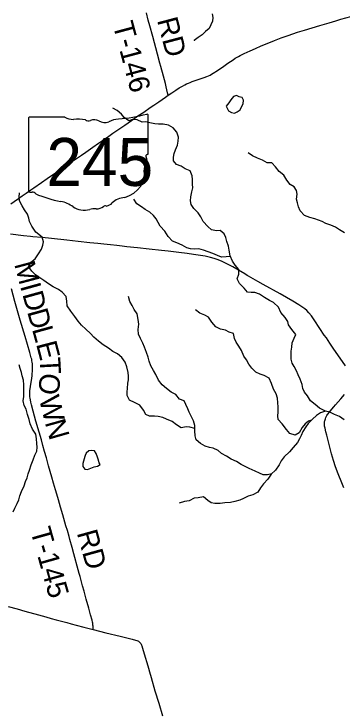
# Model space of a CAD drawing. Extents: x 0 to 1101, y 0 to 440.
# Drawn here: x 848.082 to 848.986, y 371.906 to 373.824 of the extents above; entities that cross this region are included whole.
import ezdxf

# ---------------------------------------------------------------- set-up
doc = ezdxf.new("R2010")
doc.units = 0
for name, color, linetype in [('GM_X_County_Road', 7, 'Continuous'), ('GM_X_Minor_Lake', 7, 'Continuous'), ('GM_X_Minor_River', 7, 'Continuous'), ('GM_X_State_Location', 7, 'Continuous'), ('GM_X_State_Route', 7, 'Continuous'), ('GM_X_State_Shield', 7, 'Continuous'), ('GM_X_Township_Road', 7, 'Continuous'), ('GM_X_Township_Road_Text', 7, 'Continuous')]:
    doc.layers.add(name, color=color, linetype=linetype)

msp = doc.modelspace()

# ---------------------------------------------------------------- linework, layer by layer
at = {"layer": 'GM_X_County_Road'}
for points in [[(848.9949, 372.8555), (848.9742, 372.8857), (848.9632, 372.9022), (848.9523, 372.9182), (848.9425, 372.9325), (848.9369, 372.9407), (848.9247, 372.9586), (848.9086, 372.9829), (848.9014, 372.9931), (848.8943, 373.0019), (848.8886, 373.0077), (848.8829, 373.0125), (848.8754, 373.0181), (848.8666, 373.024), (848.85, 373.034), (848.8148, 373.0538), (848.7687, 373.0795), (848.7536, 373.0881), (848.7284, 373.1027), (848.7246, 373.1049), (848.7176, 373.1089), (848.7005, 373.119), (848.6849, 373.128), (848.6701, 373.136), (848.6539, 373.1439), (848.6417, 373.1486), (848.6333, 373.1516), (848.6237, 373.1543), (848.6163, 373.1559), (848.6085, 373.1573), (848.5955, 373.1591), (848.5765, 373.1621), (848.5587, 373.1647), (848.5359, 373.1679), (848.5063, 373.1717), (848.4884, 373.1737), (848.4544, 373.1771), (848.4223, 373.1806), (848.3932, 373.1835), (848.3796, 373.185), (848.3654, 373.1868), (848.3475, 373.1888), (848.3296, 373.1906), (848.3129, 373.1925), (848.2913, 373.1947), (848.2591, 373.1982), (848.2276, 373.2016), (848.185, 373.206), (848.1769, 373.2068), (848.1584, 373.2086), (848.1336, 373.2112), (848.1275, 373.2118), (848.1077, 373.214), (848.0719, 373.2181)], [(848.9907, 372.5206), (848.985, 372.5343), (848.975, 372.5583), (848.9676, 372.578), (848.9619, 372.5951), (848.9565, 372.6141), (848.9493, 372.6431), (848.9438, 372.6648), (848.9412, 372.6744), (848.9389, 372.684), (848.9378, 372.69), (848.9373, 372.6948), (848.9372, 372.6975), (848.9374, 372.6998), (848.9378, 372.7024), (848.9382, 372.7048), (848.9388, 372.7075), (848.9397, 372.7103), (848.9408, 372.7133), (848.9421, 372.7158), (848.9436, 372.7188), (848.9453, 372.7216), (848.9465, 372.7233), (848.9526, 372.7311), (848.9633, 372.7432), (848.9678, 372.7483), (848.9825, 372.7652), (848.9926, 372.777)]]:
    msp.add_lwpolyline(points, dxfattribs=at)
at = {"layer": 'GM_X_Minor_Lake'}
for points in [[(848.7064, 373.5954), (848.7026, 373.5963), (848.6947, 373.5995), (848.6867, 373.5966), (848.679, 373.588), (848.6736, 373.5794), (848.6662, 373.5704)], [(848.6662, 373.5704), (848.6728, 373.5578), (848.6811, 373.5528), (848.6894, 373.5515), (848.697, 373.5544), (848.7046, 373.5604), (848.7089, 373.5686), (848.7129, 373.5772), (848.7145, 373.5867), (848.7109, 373.5943), (848.7064, 373.5954)], [(848.3192, 372.5848), (848.317, 372.589), (848.3138, 372.5989), (848.3116, 372.605), (848.3084, 372.6145), (848.304, 372.6221), (848.2957, 372.623), (848.2877, 372.6216), (848.2804, 372.6153), (848.2778, 372.6088)], [(848.2778, 372.6088), (848.2768, 372.6063), (848.272, 372.5875), (848.2718, 372.5788), (848.2774, 372.5715), (848.2849, 372.5707), (848.2937, 372.5747), (848.3028, 372.5779), (848.3116, 372.58), (848.3192, 372.5848)]]:
    msp.add_lwpolyline(points, dxfattribs=at)
at = {"layer": 'GM_X_Minor_River'}
for points in [[(848.6275, 373.8243), (848.6302, 373.8141), (848.6287, 373.8046), (848.6242, 373.794), (848.6192, 373.7845), (848.6098, 373.7761), (848.6003, 373.767), (848.5889, 373.7598), (848.5783, 373.7507), (848.5783, 373.7503)], [(848.9397, 372.7313), (848.9232, 372.7391), (848.9117, 372.7495), (848.899, 372.7599), (848.8909, 372.7736), (848.8827, 372.7836), (848.878, 372.7931), (848.8755, 372.8048), (848.8705, 372.8193), (848.8646, 372.8314), (848.8606, 372.8417), (848.854, 372.8539), (848.8481, 372.8634), (848.8453, 372.8744), (848.8451, 372.8869), (848.846, 372.8963), (848.847, 372.9068), (848.8487, 372.9189), (848.8538, 372.932), (848.8585, 372.9425), (848.8478, 372.9555), (848.8378, 372.9685), (848.8368, 372.9779), (848.8294, 372.989), (848.8172, 373.0024), (848.8106, 373.0176), (848.7972, 373.0299), (848.7859, 373.0354), (848.7725, 373.0443), (848.7586, 373.0532), (848.7451, 373.0579), (848.7353, 373.0581), (848.7251, 373.059), (848.7158, 373.0697), (848.7035, 373.0827), (848.6969, 373.0957), (848.7017, 373.1084), (848.7015, 373.1213), (848.6911, 373.1327), (848.6841, 373.1442), (848.6775, 373.1583), (848.6748, 373.1745), (848.6727, 373.1855), (848.6684, 373.1976), (848.6659, 373.2094), (848.6612, 373.2189), (848.65, 373.2281), (848.6401, 373.2275), (848.6265, 373.2304), (848.6157, 373.2396), (848.6027, 373.2527), (848.5969, 373.2656), (848.5895, 373.277), (848.5772, 373.2886), (848.5702, 373.2996), (848.5681, 373.3095), (848.569, 373.3212), (848.5719, 373.3347), (848.5744, 373.3456), (848.5738, 373.3562), (848.574, 373.369), (848.5727, 373.3789), (848.5672, 373.3926), (848.5533, 373.3977), (848.5425, 373.4054), (848.5293, 373.4101), (848.5211, 373.4197), (848.5213, 373.4299), (848.5234, 373.4401), (848.5273, 373.4502), (848.5321, 373.463), (848.5345, 373.4739), (848.5351, 373.4848), (848.5308, 373.4985), (848.5208, 373.5108), (848.5073, 373.5185), (848.4933, 373.521), (848.4797, 373.5212), (848.4699, 373.5222), (848.4563, 373.525), (848.445, 373.5275), (848.4352, 373.5265), (848.4216, 373.5327), (848.408, 373.5337), (848.3985, 373.5297), (848.3854, 373.539), (848.3784, 373.5485), (848.3665, 373.5589), (848.3545, 373.5652)], [(848.9925, 373.2223), (848.9787, 373.2301), (848.9675, 373.2378), (848.9551, 373.2429), (848.9415, 373.248), (848.931, 373.2527), (848.9209, 373.257), (848.9107, 373.2606), (848.8968, 373.2638), (848.8825, 373.2693), (848.8706, 373.2828), (848.8659, 373.2934), (848.8627, 373.304), (848.8602, 373.3146), (848.8623, 373.3286), (848.8602, 373.338), (848.8539, 373.3487), (848.8427, 373.3553), (848.8334, 373.3664), (848.825, 373.3805), (848.8127, 373.3909), (848.8027, 373.4039), (848.7923, 373.4147), (848.7798, 373.4145), (848.7666, 373.4215), (848.7527, 373.4274), (848.7392, 373.4336), (848.7269, 373.4418)], [(848.5802, 372.6836), (848.5664, 372.6869), (848.5566, 372.6882), (848.5422, 372.6857), (848.5295, 372.6939), (848.5179, 372.7031), (848.5021, 372.7087), (848.492, 372.7134), (848.4792, 372.7166), (848.4689, 372.7171), (848.4557, 372.7177), (848.4452, 372.7224), (848.4386, 372.7335), (848.4282, 372.7472), (848.414, 372.7546), (848.4001, 372.7617), (848.3935, 372.7742), (848.3937, 372.7844), (848.3946, 372.7938), (848.3956, 372.8078), (848.3976, 372.8175), (848.3974, 372.8274), (848.3964, 372.8372), (848.3929, 372.8535), (848.3886, 372.8664), (848.3793, 372.8786), (848.3667, 372.889), (848.3539, 372.8956), (848.342, 372.9048), (848.3274, 372.9137), (848.3147, 372.9241), (848.3016, 372.9349), (848.2931, 372.9445), (848.2797, 372.9568), (848.2681, 372.9675), (848.2588, 372.979), (848.2496, 372.992), (848.2389, 373.0061), (848.2282, 373.0214), (848.2276, 373.0342), (848.2256, 373.0463), (848.2144, 373.0582), (848.2043, 373.0655), (848.1897, 373.0733), (848.1773, 373.0818), (848.1646, 373.0903), (848.1508, 373.0996), (848.1411, 373.1065), (848.131, 373.1165), (848.1222, 373.1294), (848.1284, 373.1414), (848.1399, 373.1503), (848.1496, 373.1637), (848.1581, 373.1768), (848.161, 373.1877), (848.1634, 373.1974), (848.1591, 373.21), (848.1423, 373.2238), (848.1308, 373.2406), (848.1242, 373.2532), (848.1225, 373.2626), (848.1196, 373.2732), (848.1108, 373.2855), (848.1049, 373.2965), (848.0968, 373.3095), (848.0962, 373.32), (848.0972, 373.3321)], [(848.6781, 373.1571), (848.6665, 373.1554), (848.654, 373.1549), (848.6428, 373.1599), (848.63, 373.1647), (848.6165, 373.1694), (848.6041, 373.1745), (848.5909, 373.1778), (848.5784, 373.1772), (848.5686, 373.1777), (848.558, 373.1802), (848.5453, 373.1875), (848.5306, 373.1946), (848.5186, 373.1989), (848.5063, 373.2119), (848.4971, 373.2264), (848.4849, 373.2402), (848.479, 373.2501), (848.4735, 373.2604), (848.4664, 373.2699), (848.4564, 373.2792), (848.4436, 373.2862), (848.4332, 373.2935), (848.4205, 373.3016), (848.412, 373.3146)], [(848.7922, 372.5591), (848.7806, 372.5557), (848.7685, 372.5556), (848.7587, 372.5602), (848.7463, 372.5657), (848.7302, 372.5736), (848.7189, 372.5787), (848.7081, 372.5841), (848.6954, 372.593), (848.68, 372.5993), (848.6672, 372.6074), (848.6537, 372.6148), (848.644, 372.6225), (848.6309, 372.6292), (848.6203, 372.6316), (848.6087, 372.6348), (848.5959, 372.6418), (848.584, 372.6522), (848.5811, 372.6628), (848.5806, 372.6768), (848.5797, 372.6915), (848.5765, 372.7041), (848.5718, 372.7136), (848.5648, 372.728), (848.5608, 372.7379), (848.5554, 372.7497), (848.551, 372.76), (848.5378, 372.7639), (848.5278, 372.7766), (848.5154, 372.7835), (848.502, 372.7932), (848.4904, 372.8036), (848.4801, 372.8166), (848.4724, 372.8318), (848.4661, 372.8428), (848.4588, 372.8562), (848.4545, 372.8691), (848.4512, 372.8797), (848.4473, 372.8929), (848.4415, 372.9077), (848.4367, 372.918), (848.4305, 372.9313), (848.4254, 372.9431), (848.4241, 372.9563), (848.4255, 372.9703), (848.4242, 372.9831), (848.4215, 372.999), (848.4133, 373.0108), (848.4078, 373.0222), (848.4012, 373.0329), (848.3973, 373.0465)], [(848.9017, 372.7064), (848.8935, 372.7034), (848.8839, 372.6964), (848.8762, 372.6863), (848.868, 372.6717), (848.8565, 372.6647), (848.8415, 372.6699), (848.8326, 372.6806), (848.8204, 372.6967), (848.81, 372.7078), (848.809, 372.7187), (848.81, 372.7285), (848.8094, 372.7429), (848.8089, 372.7542), (848.8076, 372.7667), (848.804, 372.7788), (848.7966, 372.7918), (848.7912, 372.807), (848.785, 372.8218), (848.7715, 372.8292), (848.7602, 372.8328), (848.7479, 372.8383), (848.7371, 372.8494), (848.7289, 372.8601), (848.7227, 372.8722), (848.7153, 372.8826), (848.7087, 372.8978), (848.701, 372.9103), (848.6944, 372.9206), (848.6893, 372.9309), (848.6868, 372.9449), (848.6752, 372.9485), (848.6643, 372.9543), (848.6511, 372.9572), (848.6384, 372.9634), (848.6268, 372.9757), (848.6176, 372.9898), (848.6079, 372.9949), (848.5943, 373.0007), (848.5824, 373.0104)], [(848.0799, 372.4543), (848.0842, 372.4641), (848.0905, 372.4772), (848.0956, 372.4873), (848.0984, 372.4982), (848.1028, 372.5102), (848.1098, 372.5256), (848.1134, 372.5372), (848.1178, 372.5477), (848.121, 372.559), (848.1242, 372.5691), (848.1297, 372.5834), (848.1352, 372.5973), (848.1396, 372.6097), (848.1447, 372.6213), (848.1456, 372.6322), (848.145, 372.6424), (848.1437, 372.6549), (848.1417, 372.6681), (848.1332, 372.6815), (848.1267, 372.6963), (848.1238, 372.708), (848.1191, 372.7217), (848.1152, 372.7365), (848.1101, 372.7468), (848.1073, 372.7596), (848.109, 372.7713), (848.1088, 372.7807), (848.1092, 372.8037), (848.1078, 372.8162), (848.1046, 372.8283), (848.1022, 372.8378), (848.0993, 372.8484), (848.0964, 372.8583)], [(848.9397, 372.7313), (848.9268, 372.7263), (848.9149, 372.7189), (848.9042, 372.7089), (848.8926, 372.6974), (848.8864, 372.6877), (848.8779, 372.675), (848.8728, 372.6645), (848.8685, 372.6547), (848.863, 372.645), (848.8511, 372.6316), (848.8407, 372.6193), (848.8261, 372.6052), (848.8183, 372.5948), (848.8125, 372.5832), (848.8028, 372.569), (848.7905, 372.5575), (848.7815, 372.5444), (848.7692, 372.531), (848.7615, 372.5202), (848.7533, 372.5082), (848.7404, 372.5009), (848.7274, 372.4973), (848.7141, 372.4911), (848.7045, 372.486), (848.6901, 372.4821), (848.6787, 372.48), (848.6632, 372.4791), (848.6496, 372.4771), (848.6352, 372.4769), (848.6254, 372.479), (848.6157, 372.4856), (848.6041, 372.4952), (848.5897, 372.4924), (848.5787, 372.4918), (848.5642, 372.4845), (848.5517, 372.4821), (848.5368, 372.4782)], [(848.9919, 372.7071), (848.9784, 372.716), (848.9649, 372.7219), (848.9522, 372.7281), (848.9397, 372.7313)]]:
    msp.add_lwpolyline(points, dxfattribs=at)
at = {"layer": 'GM_X_State_Route'}
msp.add_lwpolyline([(848.0728, 373.3017), (848.0827, 373.3085), (848.0948, 373.3168), (848.1045, 373.3235), (848.1156, 373.331), (848.1286, 373.3399), (848.1368, 373.3455), (848.1577, 373.3601), (848.1736, 373.371), (848.1961, 373.3866), (848.2206, 373.4035), (848.2288, 373.4091), (848.2375, 373.4151), (848.2482, 373.4225), (848.2678, 373.4355), (848.2795, 373.4438), (848.2991, 373.4573), (848.3148, 373.4682), (848.3289, 373.4781), (848.3429, 373.4875), (848.3546, 373.4957), (848.371, 373.5069), (848.3872, 373.5183), (848.4055, 373.5311), (848.4235, 373.5434), (848.4394, 373.5543), (848.4574, 373.5665), (848.4672, 373.5731), (848.4811, 373.5825), (848.4995, 373.5952), (848.5069, 373.6003), (848.5165, 373.6069), (848.5282, 373.6148), (848.5371, 373.6205), (848.5463, 373.6258), (848.553, 373.6294), (848.5575, 373.6316), (848.5626, 373.6337), (848.5674, 373.6358), (848.573, 373.6379), (848.587, 373.643), (848.6058, 373.6494), (848.6133, 373.6522), (848.6181, 373.6543), (848.6224, 373.6562), (848.6263, 373.6585), (848.6304, 373.6609), (848.6423, 373.6687), (848.6596, 373.6807), (848.6709, 373.6885), (848.6854, 373.6981), (848.6917, 373.7021), (848.6971, 373.7053), (848.7008, 373.7075), (848.7052, 373.7098), (848.7159, 373.7151), (848.7328, 373.7229), (848.7476, 373.7293), (848.7629, 373.7362), (848.775, 373.7412), (848.7992, 373.7508), (848.8184, 373.7581), (848.8371, 373.7649), (848.863, 373.7737), (848.882, 373.7796), (848.9249, 373.7923), (848.9505, 373.8), (848.969, 373.8055), (848.9821, 373.8094), (849.0095, 373.8172)], dxfattribs=at)
at = {"layer": 'GM_X_State_Shield'}
for p, q in [((848.4517, 373.4407), (848.4517, 373.5454)), ((848.1222, 373.537), (848.1222, 373.3369)), ((848.2219, 373.5404), (848.1254, 373.5404)), ((848.4517, 373.4407), (848.4517, 373.4407))]:
    msp.add_line(p, q, dxfattribs=at)
for centre, major_axis, start_param, end_param in [((848.3343, 373.8133), (0.3495, 0), 4.814394, 5.042369), ((848.4481, 373.5458), (0.00367, 0), 6.141152, 7.989035), ((848.1259, 373.5374), (0.00382, 0), 1.712693, 3.28349), ((848.2449, 373.5637), (0.037, 0), 4.042523, 4.731795), ((848.2572, 373.4281), (0.133, 0), 1.404758, 1.657858), ((848.2874, 373.5385), (0.0107, 0), 3.836095, 5.185415), ((848.3031, 373.5153), (0.0222, 0), 0.950623, 2.079405), ((848.3317, 373.547), (0.0267, 0), 4.081561, 5.145723), ((848.3789, 373.4793), (0.0703, 0), 1.699011, 2.107814), ((848.4509, 373.433), (0.00568, 0), 1.883978, 3.671073), ((848.4148, 373.4198), (0.0341, 0), 5.934695, 6.695948), ((848.4478, 373.4403), (0.00393, 0), 5.05454, 6.418171), ((848.4649, 373.3969), (0.0248, 0), 2.387724, 3.262537), ((848.3539, 373.3836), (0.0874, 0), 5.101752, 6.440018), ((848.126, 373.3364), (0.00385, 0), 3.00124, 4.508301), ((848.1265, 373.3569), (0.0294, 0), 4.665946, 4.897461), ((848.1326, 373.3253), (0.0106, 0), 0.519207, 1.627899), ((848.2664, 373.5051), (0.2524, 0), 4.195997, 4.488961), ((848.3908, 373.2807), (0.0479, 0), 1.647645, 2.488434), ((848.1911, 373.247), (0.079, 0), 0.823519, 1.323587), ((848.2765, 373.3243), (0.0501, 0), 4.026481, 4.996735), ((848.3092, 373.3093), (0.0267, 0), 4.691044, 5.507374), ((848.3333, 373.29), (0.00752, 0), 1.147584, 2.315152), ((848.3301, 373.3175), (0.0282, 0), 4.937069, 5.64225), ((848.3055, 373.2551), (0.0412, 0), 1.495662, 1.94098)]:
    msp.add_ellipse(centre, major_axis=major_axis, ratio=0.8, start_param=start_param, end_param=end_param, dxfattribs=at)
at = {"layer": 'GM_X_Township_Road'}
for points in [[(848.4841, 373.6884), (848.4774, 373.7133), (848.4642, 373.7619), (848.4561, 373.7913), (848.452, 373.8069), (848.4466, 373.8273)], [(848.5069, 373.6003), (848.5053, 373.6067), (848.5011, 373.6238), (848.4989, 373.6327), (848.4935, 373.6527), (848.4864, 373.6797), (848.4841, 373.6884)], [(848.2999, 372.13), (848.2998, 372.1366), (848.2997, 372.1395), (848.2996, 372.1421), (848.2992, 372.1448), (848.2988, 372.1475), (848.2982, 372.1507), (848.297, 372.156), (848.2931, 372.1705), (848.2879, 372.189), (848.2811, 372.2135), (848.275, 372.2357), (848.2708, 372.2507), (848.2678, 372.2614), (848.2639, 372.2758), (848.2615, 372.2848), (848.2589, 372.2943), (848.2468, 372.3386), (848.242, 372.3559), (848.2358, 372.378), (848.2336, 372.3858), (848.2289, 372.4026), (848.2252, 372.4157), (848.2164, 372.4455), (848.2103, 372.467), (848.2045, 372.4867), (848.1998, 372.5028), (848.1962, 372.5147), (848.1908, 372.5332), (848.1862, 372.5499), (848.1774, 372.581), (848.1713, 372.6025), (848.1664, 372.6199), (848.1617, 372.6366), (848.1573, 372.6522), (848.151, 372.6736), (848.1421, 372.704), (848.1345, 372.7309), (848.1299, 372.7489), (848.1284, 372.7559), (848.1272, 372.7623), (848.1264, 372.7668), (848.126, 372.7708), (848.1257, 372.7751), (848.1255, 372.7788), (848.1256, 372.7827), (848.1259, 372.788), (848.1263, 372.7928), (848.1271, 372.7991), (848.1307, 372.8218), (848.1316, 372.8287), (848.1324, 372.8348), (848.1329, 372.8401), (848.1331, 372.8454), (848.1332, 372.8491), (848.1332, 372.8529), (848.133, 372.8572), (848.1326, 372.8616), (848.132, 372.8661), (848.1315, 372.8697), (848.1307, 372.874), (848.1297, 372.8782), (848.1259, 372.8927), (848.113, 372.9362), (848.0994, 372.9814), (848.0844, 373.0333), (848.0754, 373.0675)], [(848.0663, 372.194), (848.0908, 372.1871), (848.1117, 372.1812), (848.1494, 372.1706), (848.1698, 372.165), (848.1847, 372.1609), (848.1985, 372.1571), (848.2279, 372.1493), (848.2399, 372.1462), (848.2531, 372.1426), (848.2746, 372.1365), (848.2963, 372.1309), (848.2999, 372.13)], [(848.2999, 372.13), (848.3348, 372.1212), (848.3741, 372.1119), (848.4073, 372.1037), (848.417, 372.1012), (848.4202, 372.1001), (848.4228, 372.099), (848.425, 372.0978), (848.4269, 372.0964), (848.4286, 372.0948), (848.43, 372.0933), (848.4312, 372.0914), (848.4322, 372.0896), (848.4332, 372.0876), (848.4339, 372.0857), (848.4362, 372.0785), (848.4434, 372.054), (848.4478, 372.0392), (848.4522, 372.0237), (848.4549, 372.0141), (848.4594, 371.9986), (848.4704, 371.9617), (848.4807, 371.9272), (848.4914, 371.8928)]]:
    msp.add_lwpolyline(points, dxfattribs=at)

# ---------------------------------------------------------------- texts
at = {"layer": 'GM_X_State_Location'}
msp.add_text('245', height=0.000189, rotation=0, dxfattribs=at).set_placement((848.2164, 373.4098))
for s in ['s', 'r']:
    msp.add_text(s, height=0.000189, dxfattribs=at).set_placement((848.2832, 373.4236))
at = {"layer": 'GM_X_State_Shield'}
msp.add_text('245', height=0.13184, dxfattribs=at).set_placement((848.1713, 373.351))
at = {"layer": 'GM_X_Township_Road_Text'}
for s, height, rotation, p in [('RD', 0.05682, 284.7426, (848.4756, 373.8073)), ('T-146', 0.05682, 284.987, (848.3535, 373.7952)), ('M', 0.0568, 284.8293, (848.0823, 373.1362)), ('I', 0.0568, 285.4366, (848.0982, 373.0759)), ('D', 0.0568, 285.4373, (848.1045, 373.0534)), ('D', 0.0568, 285.435, (848.1178, 373.0052)), ('L', 0.0568, 285.4209, (848.1311, 372.9571)), ('E', 0.0568, 284.6308, (848.1423, 372.9163)), ('T', 0.0568, 273.07, (848.1526, 372.8782)), ('O', 0.0568, 263.091, (848.155, 372.8383)), ('W', 0.0568, 283.7817, (848.1503, 372.7664)), ('N', 0.0568, 285.8812, (848.1665, 372.7003)), ('T-145', 0.05682, 285.7208, (848.1264, 372.4031)), ('RD', 0.05682, 285.4701, (848.2546, 372.3964))]:
    msp.add_text(s, height=height, rotation=rotation, dxfattribs=at).set_placement(p)

doc.saveas('drawing.dxf')
